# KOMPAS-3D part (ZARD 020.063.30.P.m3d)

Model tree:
1. Плоскость XY
2. Плоскость ZX
3. Плоскость ZY
4. Ось X
5. Ось Y
6. Ось Z
7. Начало координат
8. Смещенная плоскость:3
     Расстояние = 97
9. Смещенная плоскость:4
     Расстояние = 97
10. Булева операция:1
11. Булева операция:2
12. Булева операция:3
13. Булева операция:4
14. Булева операция:7
15. Булева операция:8
